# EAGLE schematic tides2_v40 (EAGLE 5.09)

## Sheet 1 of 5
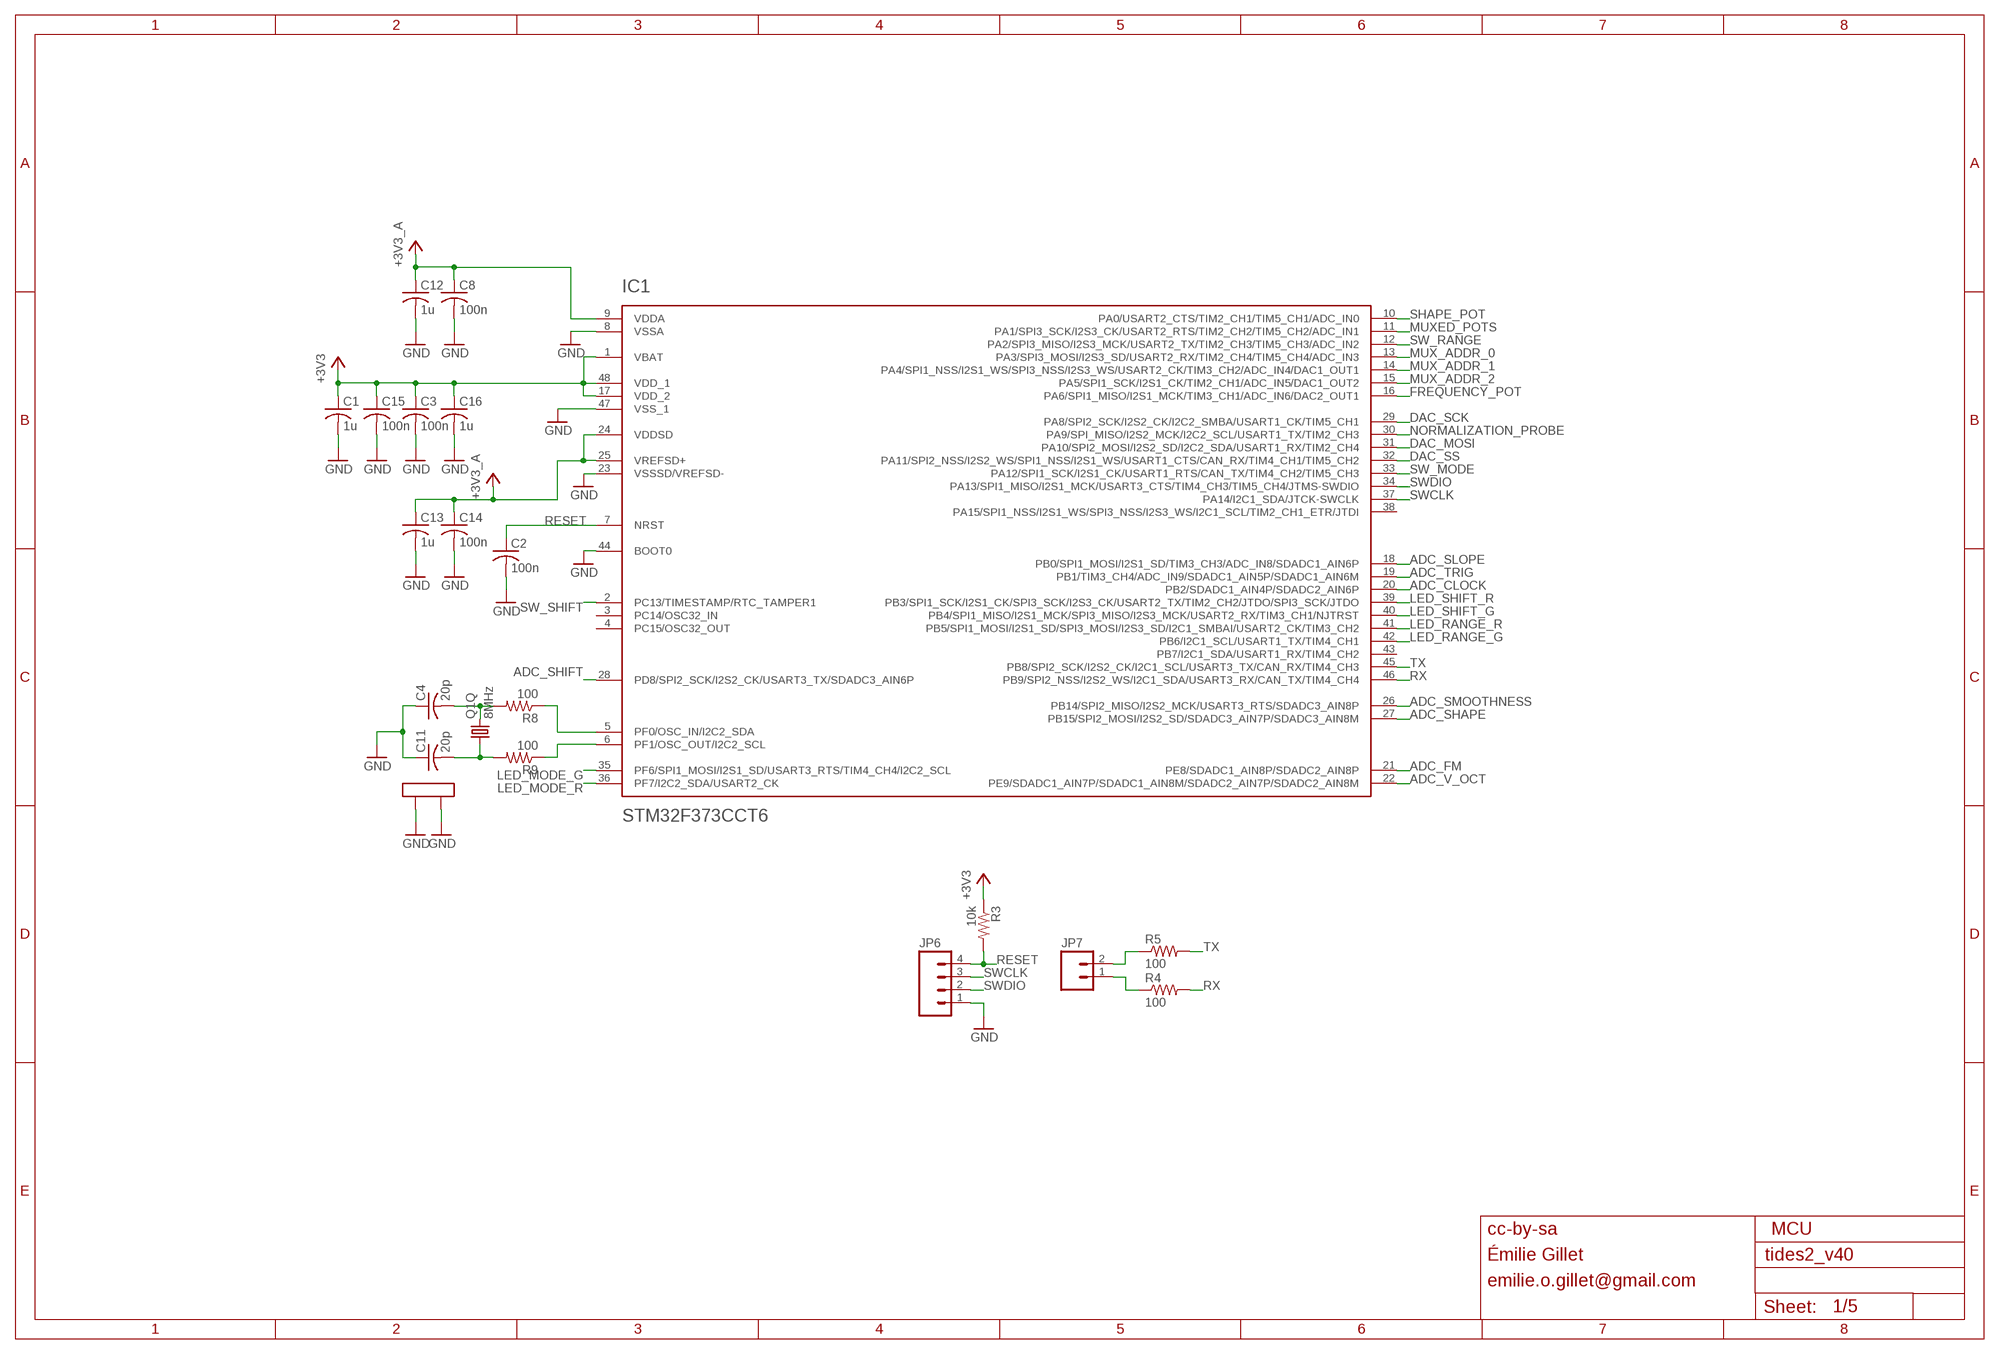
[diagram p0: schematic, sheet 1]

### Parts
C1  1u  C-USC0402  [C0402]
C2  100n  C-USC0402  [C0402]
C3  100n  C-USC0402  [C0402]
C4  20p  C-USC0402  [C0402]
C8  100n  C-USC0402  [C0402]
C11  20p  C-USC0402  [C0402]
C12  1u  C-USC0402  [C0402]
C13  1u  C-USC0402  [C0402]
C14  100n  C-USC0402  [C0402]
C15  100n  C-USC0402  [C0402]
C16  1u  C-USC0402  [C0402]
IC1  STM32F373CCT6  STM32F373C  [LQFP48]
JP6  M04PTH  [1X04]
JP7  M02PTH  [1X02]
Q1  8MHz  CRYSTAL  [CTS406]
R3  10k  R-US_R0402  [R0402]
R4  100  R-US_R0402  [R0402]
R5  100  R-US_R0402  [R0402]
R8  100  R-US_R0402  [R0402]
R9  100  R-US_R0402  [R0402]

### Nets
+3V3: C1.1 C3.1 C15.1 C16.1 IC1.1(VBAT) IC1.17(VDD_2) IC1.48(VDD_1) R3.1 ; also sheet 4,5
+3V3_A: C8.1 C12.1 C13.1 C14.1 IC1.9(VDDA) IC1.24(VDDSD) IC1.25(VREFSD+) ; also sheet 2,3,4,5
ADC_CLOCK: IC1.20(PB2/SDADC1_AIN4P/SDADC2_AIN6P) ; also sheet 3
ADC_FM: IC1.21(PE8/SDADC1_AIN8P/SDADC2_AIN8P) ; also sheet 3
ADC_SHAPE: IC1.27(PB15/SPI2_MOSI/I2S2_SD/SDADC3_AIN7P/SDADC3_AIN8M) ; also sheet 3
ADC_SHIFT: IC1.28(PD8/SPI2_SCK/I2S2_CK/USART3_TX/SDADC3_AIN6P) ; also sheet 3
ADC_SLOPE: IC1.18(PB0/SPI1_MOSI/I2S1_SD/TIM3_CH3/ADC_IN8/SDADC1_AIN6P) ; also sheet 3
ADC_SMOOTHNESS: IC1.26(PB14/SPI2_MISO/I2S2_MCK/USART3_RTS/SDADC3_AIN8P) ; also sheet 3
ADC_TRIG: IC1.19(PB1/TIM3_CH4/ADC_IN9/SDADC1_AIN5P/SDADC1_AIN6M) ; also sheet 3
ADC_V_OCT: IC1.22(PE9/SDADC1_AIN7P/SDADC1_AIN8M/SDADC2_AIN7P/SDADC2_AIN8M) ; also sheet 3
DAC_MOSI: IC1.31(PA10/SPI2_MOSI/I2S2_SD/I2C2_SDA/USART1_RX/TIM2_CH4) ; also sheet 4
DAC_SCK: IC1.29(PA8/SPI2_SCK/I2S2_CK/I2C2_SMBA/USART1_CK/TIM5_CH1) ; also sheet 4
DAC_SS: IC1.32(PA11/SPI2_NSS/I2S2_WS/SPI1_NSS/I2S1_WS/USART1_CTS/CAN_RX/TIM4_CH1/TIM5_CH2) ; also sheet 4
FREQUENCY_POT: IC1.16(PA6/SPI1_MISO/I2S1_MCK/TIM3_CH1/ADC_IN6/DAC2_OUT1) ; also sheet 2
GND: C1.2 C2.2 C3.2 C4.1 C8.2 C11.1 C12.2 C13.2 C14.2 C15.2 C16.2 IC1.8(VSSA) IC1.23(VSSSD/VREFSD-) IC1.44(BOOT0) IC1.47(VSS_1) JP6.1 Q1.2(LID1) Q1.4(LID2) ; also sheet 2,3,4,5
LED_MODE_G: IC1.35(PF6/SPI1_MOSI/I2S1_SD/USART3_RTS/TIM4_CH4/I2C2_SCL) ; also sheet 2
LED_MODE_R: IC1.36(PF7/I2C2_SDA/USART2_CK) ; also sheet 2
LED_RANGE_G: IC1.42(PB6/I2C1_SCL/USART1_TX/TIM4_CH1) ; also sheet 2
LED_RANGE_R: IC1.41(PB5/SPI1_MOSI/I2S1_SD/SPI3_MOSI/I2S3_SD/I2C1_SMBAI/USART2_CK/TIM3_CH2) ; also sheet 2
LED_SHIFT_G: IC1.40(PB4/SPI1_MISO/I2S1_MCK/SPI3_MISO/I2S3_MCK/USART2_RX/TIM3_CH1/NJTRST) ; also sheet 2
LED_SHIFT_R: IC1.39(PB3/SPI1_SCK/I2S1_CK/SPI3_SCK/I2S3_CK/USART2_TX/TIM2_CH2/JTDO/SPI3_SCK/JTDO) ; also sheet 2
MUX_ADDR_0: IC1.13(PA3/SPI3_MOSI/I2S3_SD/USART2_RX/TIM2_CH4/TIM5_CH4/ADC_IN3) ; also sheet 2
MUX_ADDR_1: IC1.14(PA4/SPI1_NSS/I2S1_WS/SPI3_NSS/I2S3_WS/USART2_CK/TIM3_CH2/ADC_IN4/DAC1_OUT1) ; also sheet 2
MUX_ADDR_2: IC1.15(PA5/SPI1_SCK/I2S1_CK/TIM2_CH1/ADC_IN5/DAC1_OUT2) ; also sheet 2
MUXED_POTS: IC1.11(PA1/SPI3_SCK/I2S3_CK/USART2_RTS/TIM2_CH2/TIM5_CH2/ADC_IN1) ; also sheet 2
N$7: IC1.5(PF0/OSC_IN/I2C2_SDA) R8.1
N$8: IC1.6(PF1/OSC_OUT/I2C2_SCL) R9.1
N$29: C4.2 Q1.3 R8.2
N$33: JP7.2 R5.1
N$35: C11.2 Q1.1 R9.2
N$51: JP7.1 R4.1
NORMALIZATION_PROBE: IC1.30(PA9/SPI_MISO/I2S2_MCK/I2C2_SCL/USART1_TX/TIM2_CH3) ; also sheet 3
RESET: C2.1 IC1.7(NRST) JP6.4 R3.2
RX: IC1.46(PB9/SPI2_NSS/I2S2_WS/I2C1_SDA/USART3_RX/CAN_TX/TIM4_CH4) R4.2
SHAPE_POT: IC1.10(PA0/USART2_CTS/TIM2_CH1/TIM5_CH1/ADC_IN0) ; also sheet 2
SW_MODE: IC1.33(PA12/SPI1_SCK/I2S1_CK/USART1_RTS/CAN_TX/TIM4_CH2/TIM5_CH3) ; also sheet 2
SW_RANGE: IC1.12(PA2/SPI3_MISO/I2S3_MCK/USART2_TX/TIM2_CH3/TIM5_CH3/ADC_IN2) ; also sheet 2
SW_SHIFT: IC1.2(PC13/TIMESTAMP/RTC_TAMPER1) ; also sheet 2
SWCLK: IC1.37(PA14/I2C1_SDA/JTCK-SWCLK) JP6.3
SWDIO: IC1.34(PA13/SPI1_MISO/I2S1_MCK/USART3_CTS/TIM4_CH3/TIM5_CH4/JTMS-SWDIO) JP6.2
TX: IC1.45(PB8/SPI2_SCK/I2S2_CK/I2C1_SCL/USART3_TX/CAN_RX/TIM4_CH3) R5.2
Unconnected: IC1.3(PC14/OSC32_IN) IC1.4(PC15/OSC32_OUT) IC1.38(PA15/SPI1_NSS/I2S1_WS/SPI3_NSS/I2S3_WS/I2C1_SCL/TIM2_CH1_ETR/JTDI) IC1.43(PB7/I2C1_SDA/USART1_RX/TIM4_CH2)

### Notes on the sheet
- cc-by-sa | MCU
- Émilie Gillet
- emilie.o.gillet@gmail.com

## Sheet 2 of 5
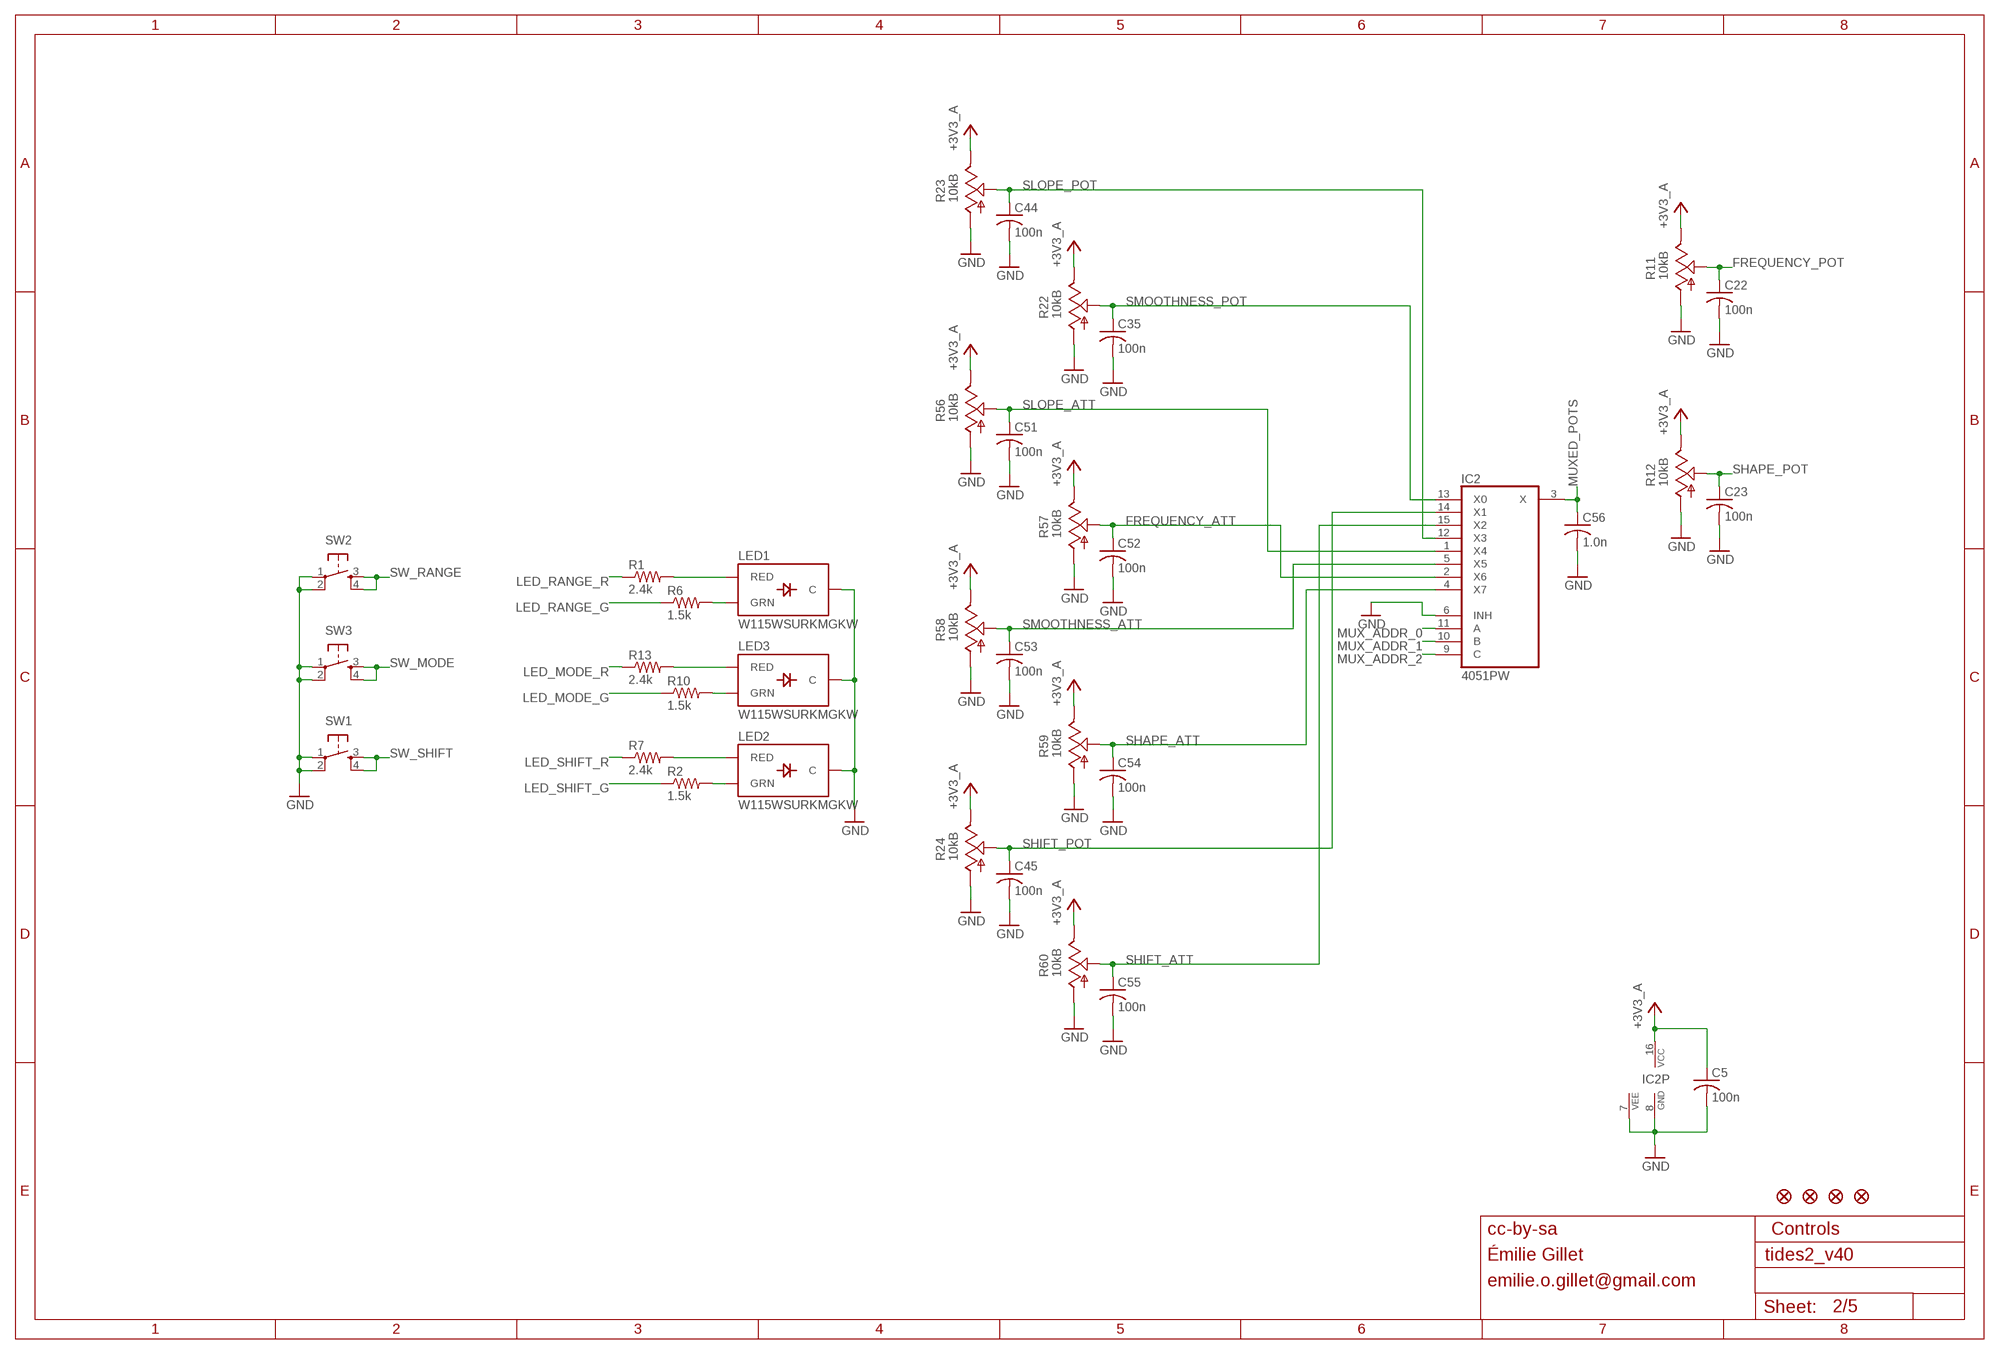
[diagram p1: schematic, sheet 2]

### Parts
C5  100n  C-USC0402  [C0402]
C22  100n  C-USC0402  [C0402]
C23  100n  C-USC0402  [C0402]
C35  100n  C-USC0402  [C0402]
C44  100n  C-USC0402  [C0402]
C45  100n  C-USC0402  [C0402]
C51  100n  C-USC0402  [C0402]
C52  100n  C-USC0402  [C0402]
C53  100n  C-USC0402  [C0402]
C54  100n  C-USC0402  [C0402]
C55  100n  C-USC0402  [C0402]
C56  1.0n  C-USC0402  [C0402]
IC2  4051PW  [TSSOP16_065]
JP1  FIDUCIAL1X2  [FIDUCIAL-1X2]
JP2  FIDUCIAL1X2  [FIDUCIAL-1X2]
JP3  FIDUCIAL1X2  [FIDUCIAL-1X2]
JP4  FIDUCIAL1X2  [FIDUCIAL-1X2]
LED1  W115WSURKMGKW  LED-BICOLOR-THROUGHHOLE2.54  [LED-BICOLOR-THROUGHHOLE-2.54]
LED2  W115WSURKMGKW  LED-BICOLOR-THROUGHHOLE2.54  [LED-BICOLOR-THROUGHHOLE-2.54]
LED3  W115WSURKMGKW  LED-BICOLOR-THROUGHHOLE2.54  [LED-BICOLOR-THROUGHHOLE-2.54]
R1  2.4k  R-US_R0402  [R0402]
R2  1.5k  R-US_R0402  [R0402]
R6  1.5k  R-US_R0402  [R0402]
R7  2.4k  R-US_R0402  [R0402]
R10  1.5k  R-US_R0402  [R0402]
R11  10kB  POT_USVERTICAL_PS  [ALPS_POT_VERTICAL_PS]
R12  10kB  POT_USVERTICAL_PS  [ALPS_POT_VERTICAL_PS]
R13  2.4k  R-US_R0402  [R0402]
R22  10kB  POT_USVERTICAL_PS  [ALPS_POT_VERTICAL_PS]
R23  10kB  POT_USVERTICAL_PS  [ALPS_POT_VERTICAL_PS]
R24  10kB  POT_USVERTICAL_PS  [ALPS_POT_VERTICAL_PS]
R56  10kB  POT_USVERTICAL  [ALPS_POT_VERTICAL]
R57  10kB  POT_USVERTICAL  [ALPS_POT_VERTICAL]
R58  10kB  POT_USVERTICAL  [ALPS_POT_VERTICAL]
R59  10kB  POT_USVERTICAL  [ALPS_POT_VERTICAL]
R60  10kB  POT_USVERTICAL  [ALPS_POT_VERTICAL]
SW1  TAC_SWITCHPTH  [TACTILE-PTH]
SW2  TAC_SWITCHPTH  [TACTILE-PTH]
SW3  TAC_SWITCHPTH  [TACTILE-PTH]

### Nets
+3V3_A: C5.1 IC2.16(VCC) R11.P$1(E) R12.P$1(E) R22.P$1(E) R23.P$1(E) R24.P$1(E) R56.P$1(E) R57.P$1(E) R58.P$1(E) R59.P$1(E) R60.P$1(E) ; also sheet 1,3,4,5
FREQUENCY_ATT: C52.1 IC2.2(X6) R57.P$2(S)
FREQUENCY_POT: C22.1 R11.P$2(S) ; also sheet 1
GND: C5.2 C22.2 C23.2 C35.2 C44.2 C45.2 C51.2 C52.2 C53.2 C54.2 C55.2 C56.2 IC2.6(INH) IC2.7(VEE) IC2.8(GND) LED1.2(C) LED2.2(C) LED3.2(C) R11.P$3(A) R12.P$3(A) R22.P$3(A) R23.P$3(A) R24.P$3(A) R56.P$3(A) R57.P$3(A) R58.P$3(A) R59.P$3(A) R60.P$3(A) SW1.1 SW1.2 SW2.1 SW2.2 SW3.1 SW3.2 ; also sheet 1,3,4,5
LED_MODE_G: R10.1 ; also sheet 1
LED_MODE_R: R13.1 ; also sheet 1
LED_RANGE_G: R6.1 ; also sheet 1
LED_RANGE_R: R1.1 ; also sheet 1
LED_SHIFT_G: R2.1 ; also sheet 1
LED_SHIFT_R: R7.1 ; also sheet 1
MUX_ADDR_0: IC2.11(A) ; also sheet 1
MUX_ADDR_1: IC2.10(B) ; also sheet 1
MUX_ADDR_2: IC2.9(C) ; also sheet 1
MUXED_POTS: C56.1 IC2.3(X) ; also sheet 1
N$16: LED1.3(RED) R1.2
N$18: LED3.3(RED) R13.2
N$20: LED3.1(GRN) R10.2
N$21: LED2.3(RED) R7.2
N$22: LED1.1(GRN) R6.2
N$23: LED2.1(GRN) R2.2
SHAPE_ATT: C54.1 IC2.4(X7) R59.P$2(S)
SHAPE_POT: C23.1 R12.P$2(S) ; also sheet 1
SHIFT_ATT: C55.1 IC2.15(X2) R60.P$2(S)
SHIFT_POT: C45.1 IC2.14(X1) R24.P$2(S)
SLOPE_ATT: C51.1 IC2.1(X4) R56.P$2(S)
SLOPE_POT: C44.1 IC2.12(X3) R23.P$2(S)
SMOOTHNESS_ATT: C53.1 IC2.5(X5) R58.P$2(S)
SMOOTHNESS_POT: C35.1 IC2.13(X0) R22.P$2(S)
SW_MODE: SW3.3 SW3.4 ; also sheet 1
SW_RANGE: SW2.3 SW2.4 ; also sheet 1
SW_SHIFT: SW1.3 SW1.4 ; also sheet 1

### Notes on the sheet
- cc-by-sa | Controls
- Émilie Gillet
- emilie.o.gillet@gmail.com

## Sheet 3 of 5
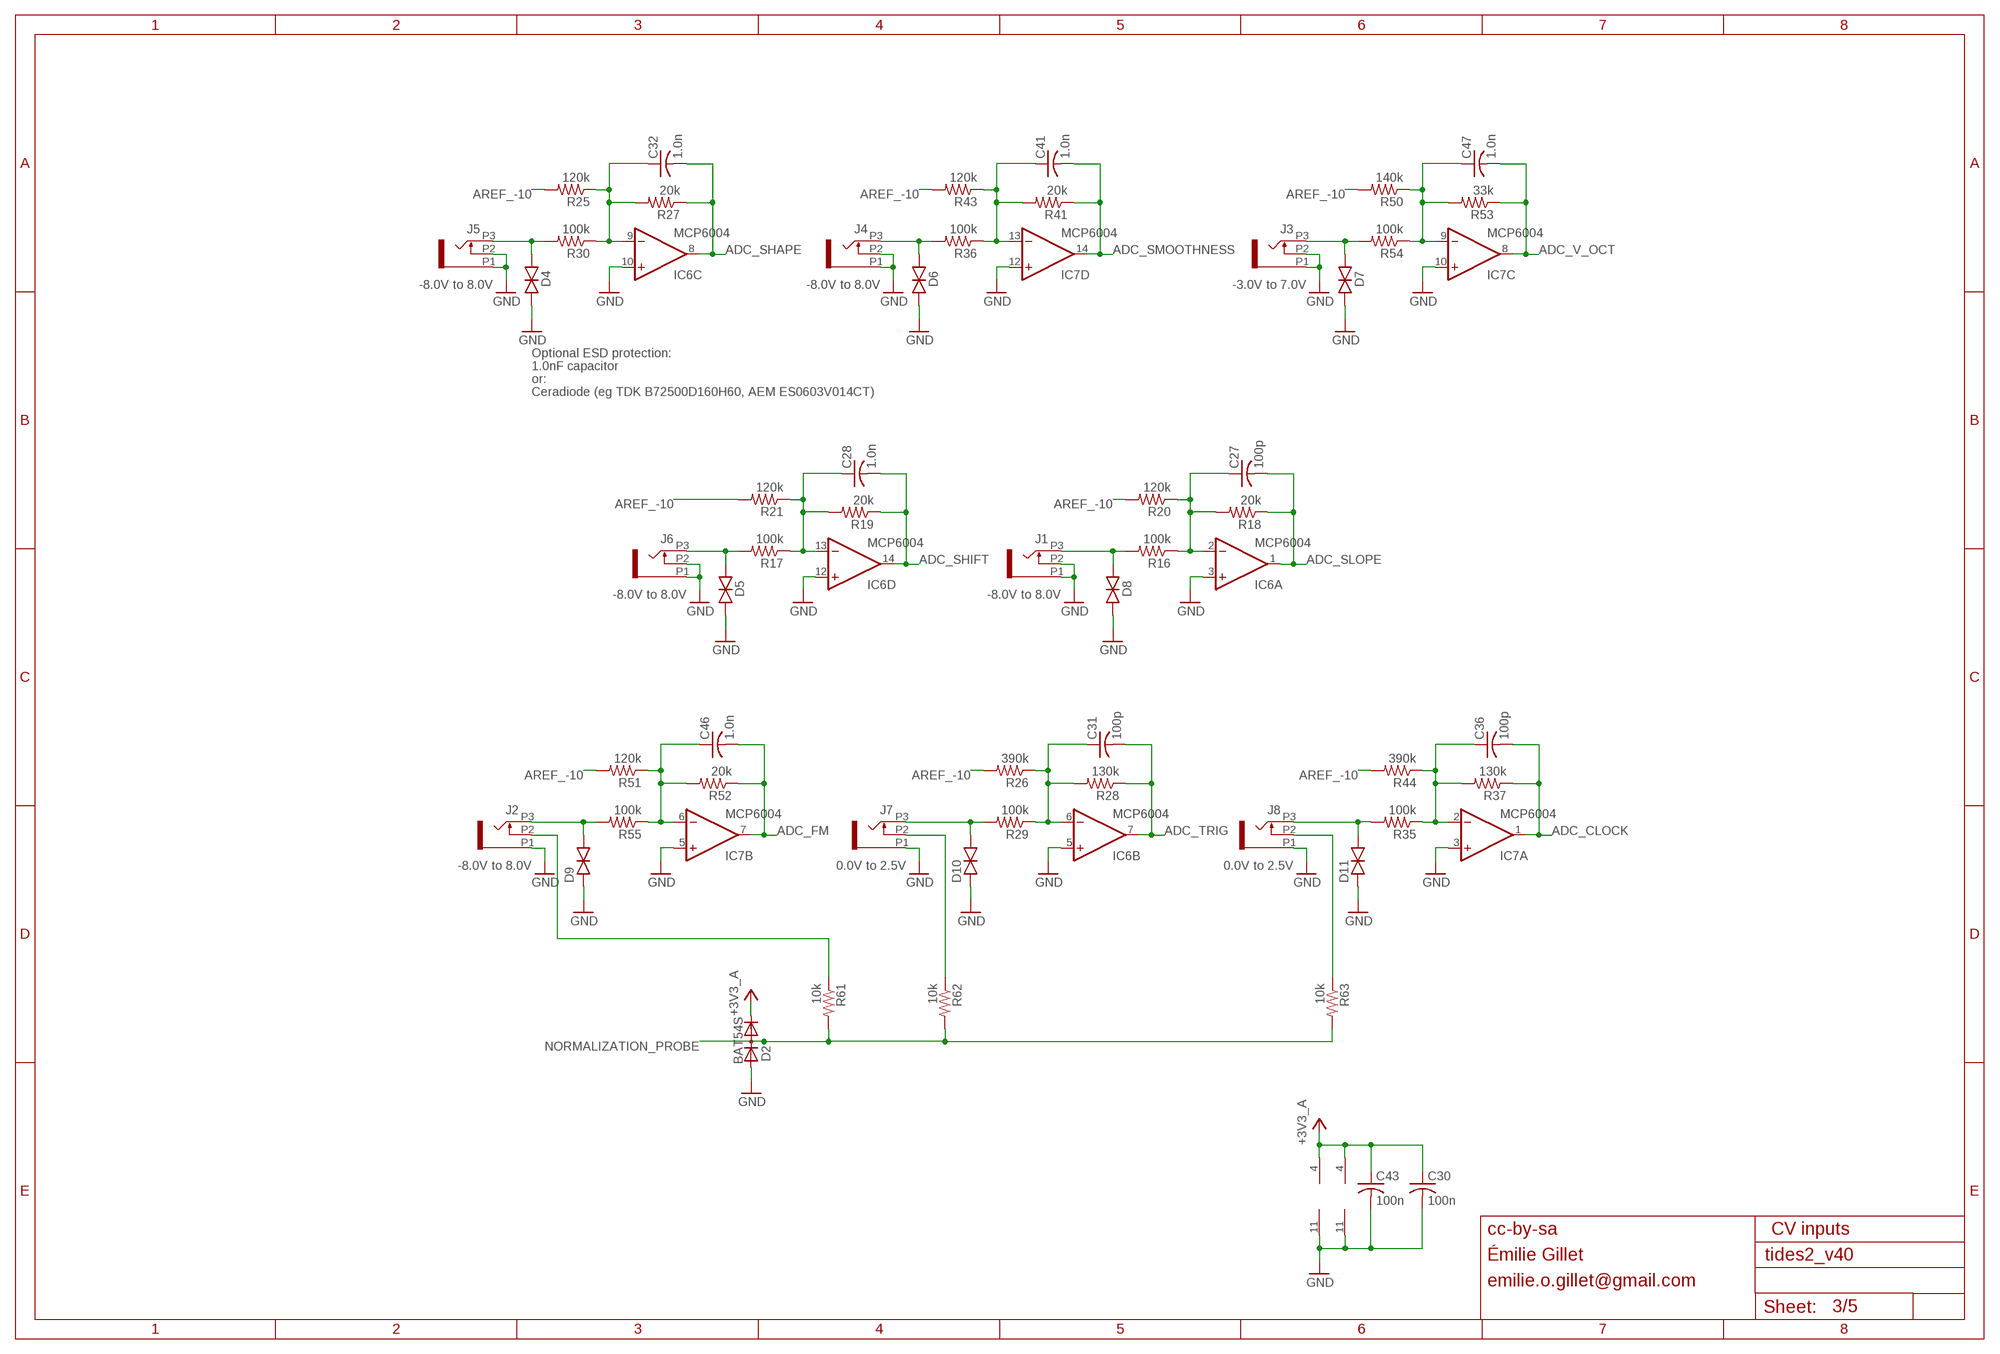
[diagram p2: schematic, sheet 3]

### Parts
C27  100p  C-USC0402  [C0402]
C28  1.0n  C-USC0402  [C0402]
C30  100n  C-USC0402  [C0402]
C31  100p  C-USC0402  [C0402]
C32  1.0n  C-USC0402  [C0402]
C36  100p  C-USC0402  [C0402]
C41  1.0n  C-USC0402  [C0402]
C43  100n  C-USC0402  [C0402]
C46  1.0n  C-USC0402  [C0402]
C47  1.0n  C-USC0402  [C0402]
D2  BAT54S  DIODE_2CACA-SOT23  [SOT23]
D4  TVS  [0603]
D5  TVS  [0603]
D6  TVS  [0603]
D7  TVS  [0603]
D8  TVS  [0603]
D9  TVS  [0603]
D10  TVS  [0603]
D11  TVS  [0603]
IC6  MCP6004  TL074PW  [TSSOP14_065]
IC7  MCP6004  TL074PW  [TSSOP14_065]
J1  PJ301_THONKICONN6  [WQP_PJ_301M6]
J2  PJ301_THONKICONN6  [WQP_PJ_301M6]
J3  PJ301_THONKICONN6  [WQP_PJ_301M6]
J4  PJ301_THONKICONN6  [WQP_PJ_301M6]
J5  PJ301_THONKICONN6  [WQP_PJ_301M6]
J6  PJ301_THONKICONN6  [WQP_PJ_301M6]
J7  PJ301_THONKICONN6  [WQP_PJ_301M6]
J8  PJ301_THONKICONN6  [WQP_PJ_301M6]
R16  100k  R-US_R0402  [R0402]
R17  100k  R-US_R0402  [R0402]
R18  20k  R-US_R0402  [R0402]
R19  20k  R-US_R0402  [R0402]
R20  120k  R-US_R0402  [R0402]
R21  120k  R-US_R0402  [R0402]
R25  120k  R-US_R0402  [R0402]
R26  390k  R-US_R0402  [R0402]
R27  20k  R-US_R0402  [R0402]
R28  130k  R-US_R0402  [R0402]
R29  100k  R-US_R0402  [R0402]
R30  100k  R-US_R0402  [R0402]
R35  100k  R-US_R0402  [R0402]
R36  100k  R-US_R0402  [R0402]
R37  130k  R-US_R0402  [R0402]
R41  20k  R-US_R0402  [R0402]
R43  120k  R-US_R0402  [R0402]
R44  390k  R-US_R0402  [R0402]
R50  140k  R-US_R0402  [R0402]
R51  120k  R-US_R0402  [R0402]
R52  20k  R-US_R0402  [R0402]
R53  33k  R-US_R0402  [R0402]
R54  100k  R-US_R0402  [R0402]
R55  100k  R-US_R0402  [R0402]
R61  10k  R-US_R0402  [R0402]
R62  10k  R-US_R0402  [R0402]
R63  10k  R-US_R0402  [R0402]

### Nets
+3V3_A: C30.1 C43.1 D2.2(C) IC6.4(P:V+) IC7.4(P:V+) ; also sheet 1,2,4,5
ADC_CLOCK: C36.2 IC7.1(A:OUT) R37.1 ; also sheet 1
ADC_FM: C46.2 IC7.7(B:OUT) R52.1 ; also sheet 1
ADC_SHAPE: C32.2 IC6.8(C:OUT) R27.1 ; also sheet 1
ADC_SHIFT: C28.2 IC6.14(D:OUT) R19.1 ; also sheet 1
ADC_SLOPE: C27.2 IC6.1(A:OUT) R18.1 ; also sheet 1
ADC_SMOOTHNESS: C41.2 IC7.14(D:OUT) R41.1 ; also sheet 1
ADC_TRIG: C31.2 IC6.7(B:OUT) R28.1 ; also sheet 1
ADC_V_OCT: C47.2 IC7.8(C:OUT) R53.1 ; also sheet 1
AREF_-10: R20.2 R21.2 R25.2 R26.2 R43.2 R44.2 R50.2 R51.2 ; also sheet 5
CLOCK_IN: D11.2(C) J8.P3 R35.2
FM_IN: D9.2(C) J2.P3 R55.2
GND: C30.2 C43.2 D2.1(A) D4.1(A) D5.1(A) D6.1(A) D7.1(A) D8.1(A) D9.1(A) D10.1(A) D11.1(A) IC6.3(A:+IN) IC6.5(B:+IN) IC6.10(C:+IN) IC6.11(P:V-) IC6.12(D:+IN) IC7.3(A:+IN) IC7.5(B:+IN) IC7.10(C:+IN) IC7.11(P:V-) IC7.12(D:+IN) J1.P1 J1.P2 J2.P1 J3.P1 J3.P2 J4.P1 J4.P2 J5.P1 J5.P2 J6.P1 J6.P2 J7.P1 J8.P1 ; also sheet 1,2,4,5
N$2: J7.P2 R62.1
N$3: J8.P2 R63.1
N$4: C27.1 IC6.2(A:-IN) R16.1 R18.2 R20.1
N$26: J2.P2 R61.1
N$28: C28.1 IC6.13(D:-IN) R17.1 R19.2 R21.1
N$30: C47.1 IC7.9(C:-IN) R50.1 R53.2 R54.1
N$32: C46.1 IC7.6(B:-IN) R51.1 R52.2 R55.1
N$34: C31.1 IC6.6(B:-IN) R26.1 R28.2 R29.1
N$37: C32.1 IC6.9(C:-IN) R25.1 R27.2 R30.1
N$39: C36.1 IC7.2(A:-IN) R35.1 R37.2 R44.1
N$41: C41.1 IC7.13(D:-IN) R36.1 R41.2 R43.1
NORMALIZATION_PROBE: D2.3(AC) R61.2 R62.2 R63.2 ; also sheet 1
SHAPE_IN: D4.2(C) J5.P3 R30.2
SHIFT_IN: D5.2(C) J6.P3 R17.2
SLOPE_IN: D8.2(C) J1.P3 R16.2
SMOOTHNESS_IN: D6.2(C) J4.P3 R36.2
TRIG_IN: D10.2(C) J7.P3 R29.2
V_OCT_IN: D7.2(C) J3.P3 R54.2

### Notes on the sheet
- -8.0V to 8.0V | -8.0V to 8.0V | -3.0V to 7.0V
- Optional ESD protection:
- 1.0nF capacitor
- or:
- Ceradiode (eg TDK B72500D160H60, AEM ES0603V014CT)
- -8.0V to 8.0V | -8.0V to 8.0V
- -8.0V to 8.0V | 0.0V to 2.5V | 0.0V to 2.5V
- cc-by-sa | CV inputs
- Émilie Gillet
- emilie.o.gillet@gmail.com

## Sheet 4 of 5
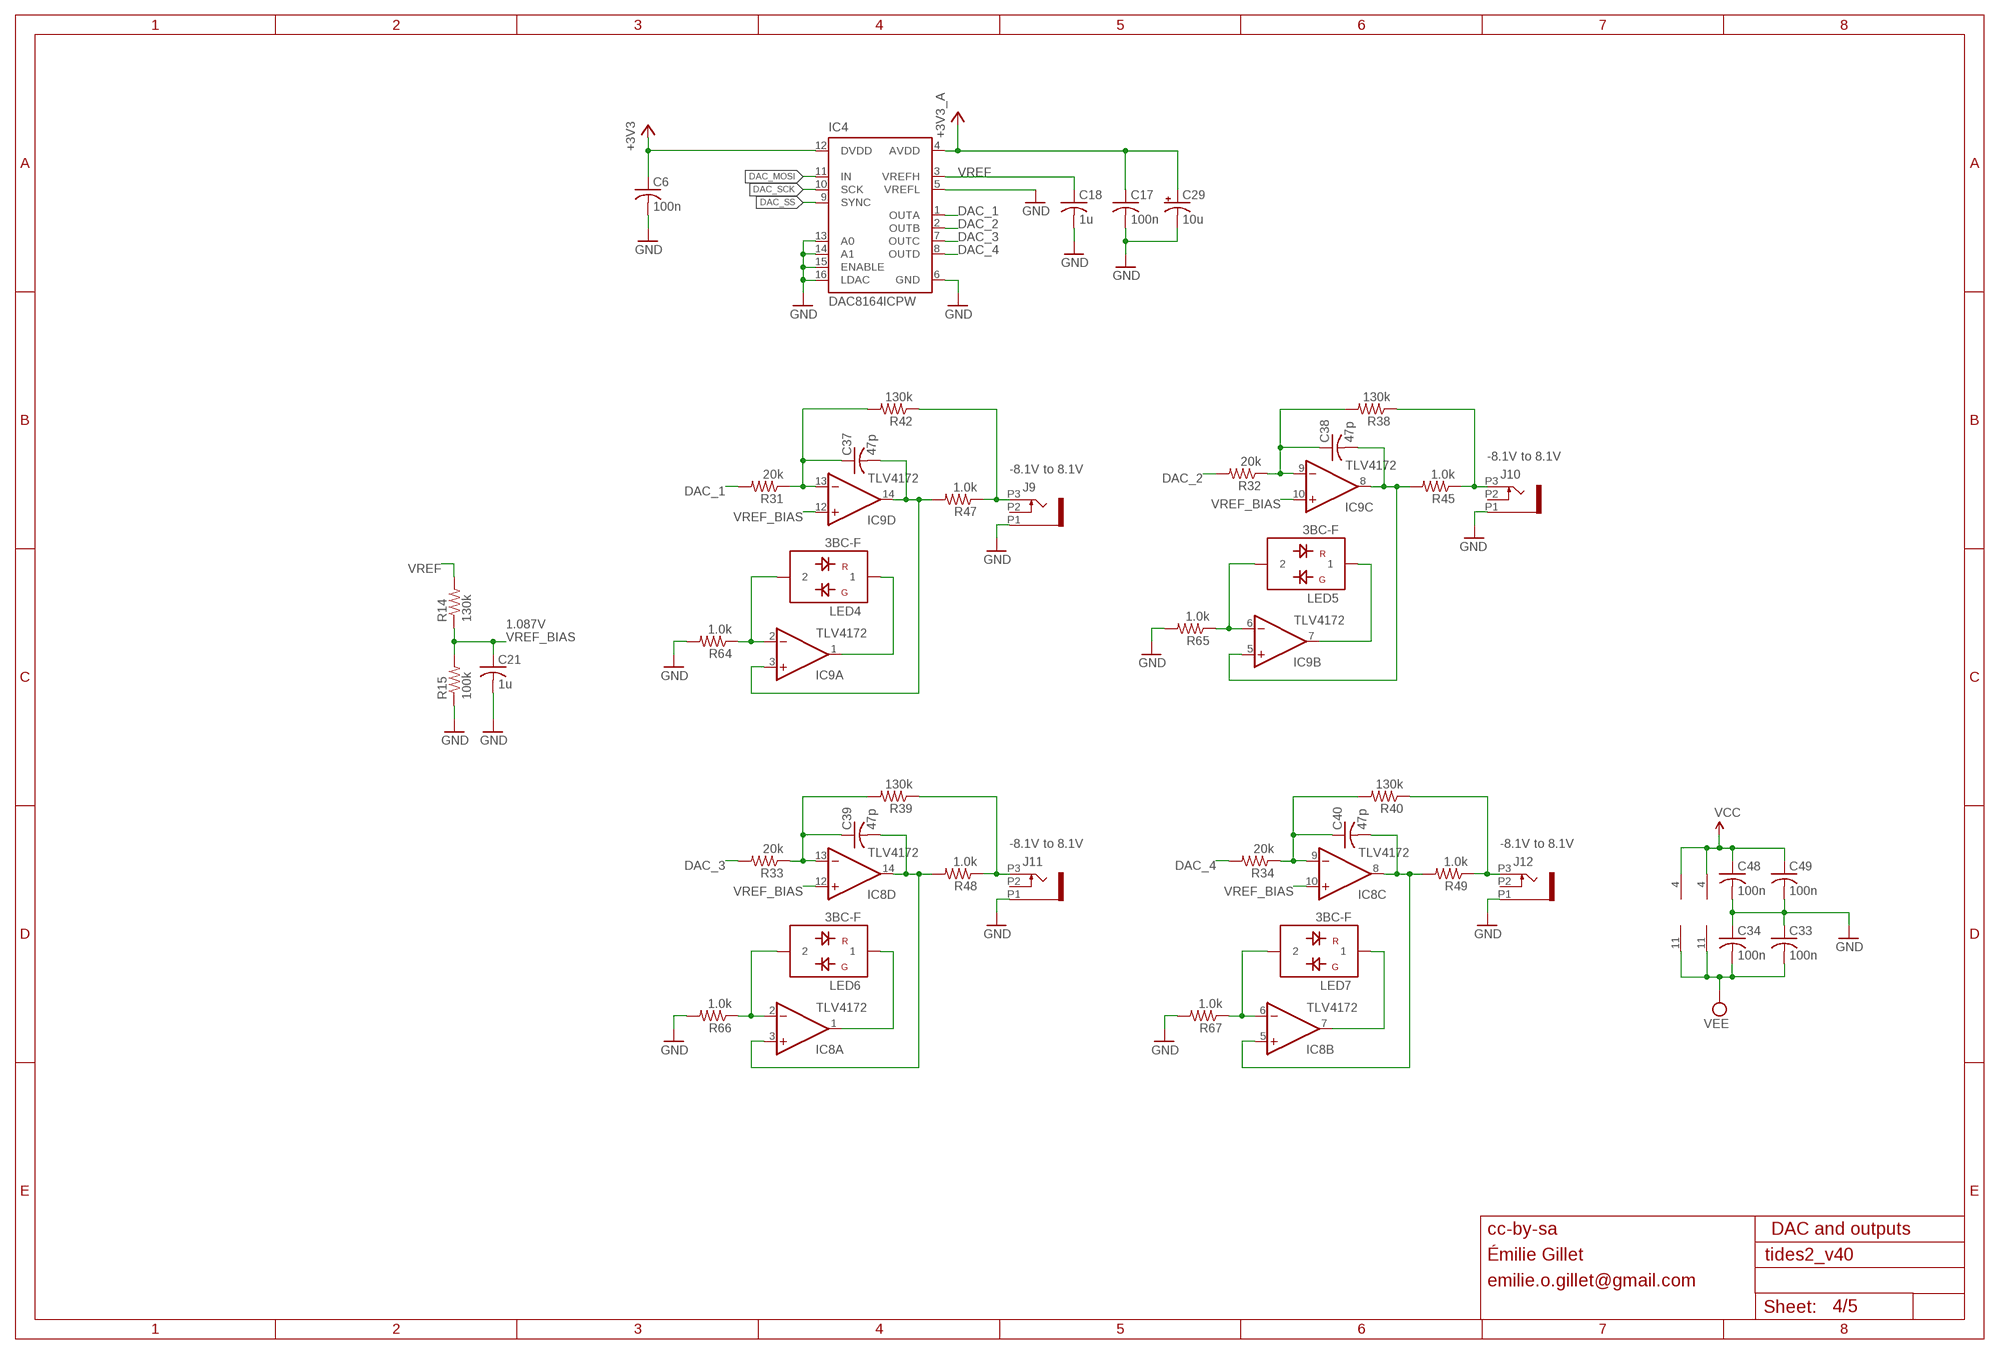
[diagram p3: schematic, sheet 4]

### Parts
C6  100n  C-USC0402  [C0402]
C17  100n  C-USC0402  [C0402]
C18  1u  C-USC0402  [C0402]
C21  1u  C-USC0402  [C0402]
C29  10u  CPOL-USA  [PANASONIC_A]
C33  100n  C-USC0402  [C0402]
C34  100n  C-USC0402  [C0402]
C37  47p  C-USC0402  [C0402]
C38  47p  C-USC0402  [C0402]
C39  47p  C-USC0402  [C0402]
C40  47p  C-USC0402  [C0402]
C48  100n  C-USC0402  [C0402]
C49  100n  C-USC0402  [C0402]
IC4  DAC8164ICPW  DAC8564  [SOP65P640X110-16N]
IC8  TLV4172  TL074PW  [TSSOP14_065]
IC9  TLV4172  TL074PW  [TSSOP14_065]
J9  PJ301_THONKICONN6  [WQP_PJ_301M6]
J10  PJ301_THONKICONN6  [WQP_PJ_301M6]
J11  PJ301_THONKICONN6  [WQP_PJ_301M6]
J12  PJ301_THONKICONN6  [WQP_PJ_301M6]
LED4  3BC-F  LED-BICOLOR-SHARED-THROUGHHOLE  [LED3MM]
LED5  3BC-F  LED-BICOLOR-SHARED-THROUGHHOLE  [LED3MM]
LED6  3BC-F  LED-BICOLOR-SHARED-THROUGHHOLE  [LED3MM]
LED7  3BC-F  LED-BICOLOR-SHARED-THROUGHHOLE  [LED3MM]
R14  130k  R-US_R0402  [R0402]
R15  100k  R-US_R0402  [R0402]
R31  20k  R-US_R0402  [R0402]
R32  20k  R-US_R0402  [R0402]
R33  20k  R-US_R0402  [R0402]
R34  20k  R-US_R0402  [R0402]
R38  130k  R-US_R0402  [R0402]
R39  130k  R-US_R0402  [R0402]
R40  130k  R-US_R0402  [R0402]
R42  130k  R-US_R0402  [R0402]
R45  1.0k  R-US_R0603  [R0603]
R47  1.0k  R-US_R0603  [R0603]
R48  1.0k  R-US_R0603  [R0603]
R49  1.0k  R-US_R0603  [R0603]
R64  1.0k  R-US_R0402  [R0402]
R65  1.0k  R-US_R0402  [R0402]
R66  1.0k  R-US_R0402  [R0402]
R67  1.0k  R-US_R0402  [R0402]

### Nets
+3V3: C6.1 IC4.12(DVDD) ; also sheet 1,5
+3V3_A: C17.1 C29.+ IC4.4(AVDD) ; also sheet 1,2,3,5
DAC_1: IC4.1(OUTA) R31.2
DAC_2: IC4.2(OUTB) R32.2
DAC_3: IC4.7(OUTC) R33.2
DAC_4: IC4.8(OUTD) R34.2
DAC_MOSI: IC4.11(IN) ; also sheet 1
DAC_SCK: IC4.10(SCK) ; also sheet 1
DAC_SS: IC4.9(SYNC) ; also sheet 1
GND: C6.2 C17.2 C18.2 C21.2 C29.- C33.1 C34.1 C48.2 C49.2 IC4.5(VREFL) IC4.6(GND) IC4.13(A0) IC4.14(A1) IC4.15(ENABLE) IC4.16(LDAC) J9.P1 J10.P1 J11.P1 J12.P1 R15.1 R64.2 R65.2 R66.2 R67.2 ; also sheet 1,2,3,5
N$45: C37.2 IC9.3(A:+IN) IC9.14(D:OUT) R47.2
N$49: J11.P3 R39.1 R48.1
N$53: J9.P3 R42.1 R47.1
N$54: C39.1 IC8.13(D:-IN) R33.1 R39.2
N$58: J12.P3 R40.1 R49.1
N$59: C40.1 IC8.9(C:-IN) R34.1 R40.2
N$60: C38.1 IC9.9(C:-IN) R32.1 R38.2
N$61: C37.1 IC9.13(D:-IN) R31.1 R42.2
N$63: J10.P3 R38.1 R45.1
N$67: IC9.2(A:-IN) LED4.2 R64.1
N$68: IC9.1(A:OUT) LED4.1
N$70: C38.2 IC9.5(B:+IN) IC9.8(C:OUT) R45.2
N$71: IC9.6(B:-IN) LED5.2 R65.1
N$72: IC9.7(B:OUT) LED5.1
N$73: C39.2 IC8.3(A:+IN) IC8.14(D:OUT) R48.2
N$74: IC8.2(A:-IN) LED6.2 R66.1
N$75: IC8.1(A:OUT) LED6.1
N$76: C40.2 IC8.5(B:+IN) IC8.8(C:OUT) R49.2
N$77: IC8.6(B:-IN) LED7.2 R67.1
N$78: IC8.7(B:OUT) LED7.1
VCC: C48.1 C49.1 IC8.4(P:V+) IC9.4(P:V+) ; also sheet 5
VEE: C33.2 C34.2 IC8.11(P:V-) IC9.11(P:V-) ; also sheet 5
VREF: C18.1 IC4.3(VREFH) R14.2
VREF_BIAS: C21.1 IC8.10(C:+IN) IC8.12(D:+IN) IC9.10(C:+IN) IC9.12(D:+IN) R14.1 R15.2
Unconnected: J9.P2 J10.P2 J11.P2 J12.P2

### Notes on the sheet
- -8.1V to 8.1V
- -8.1V to 8.1V
- 1.087V
- -8.1V to 8.1V | -8.1V to 8.1V
- cc-by-sa | DAC and outputs
- Émilie Gillet
- emilie.o.gillet@gmail.com

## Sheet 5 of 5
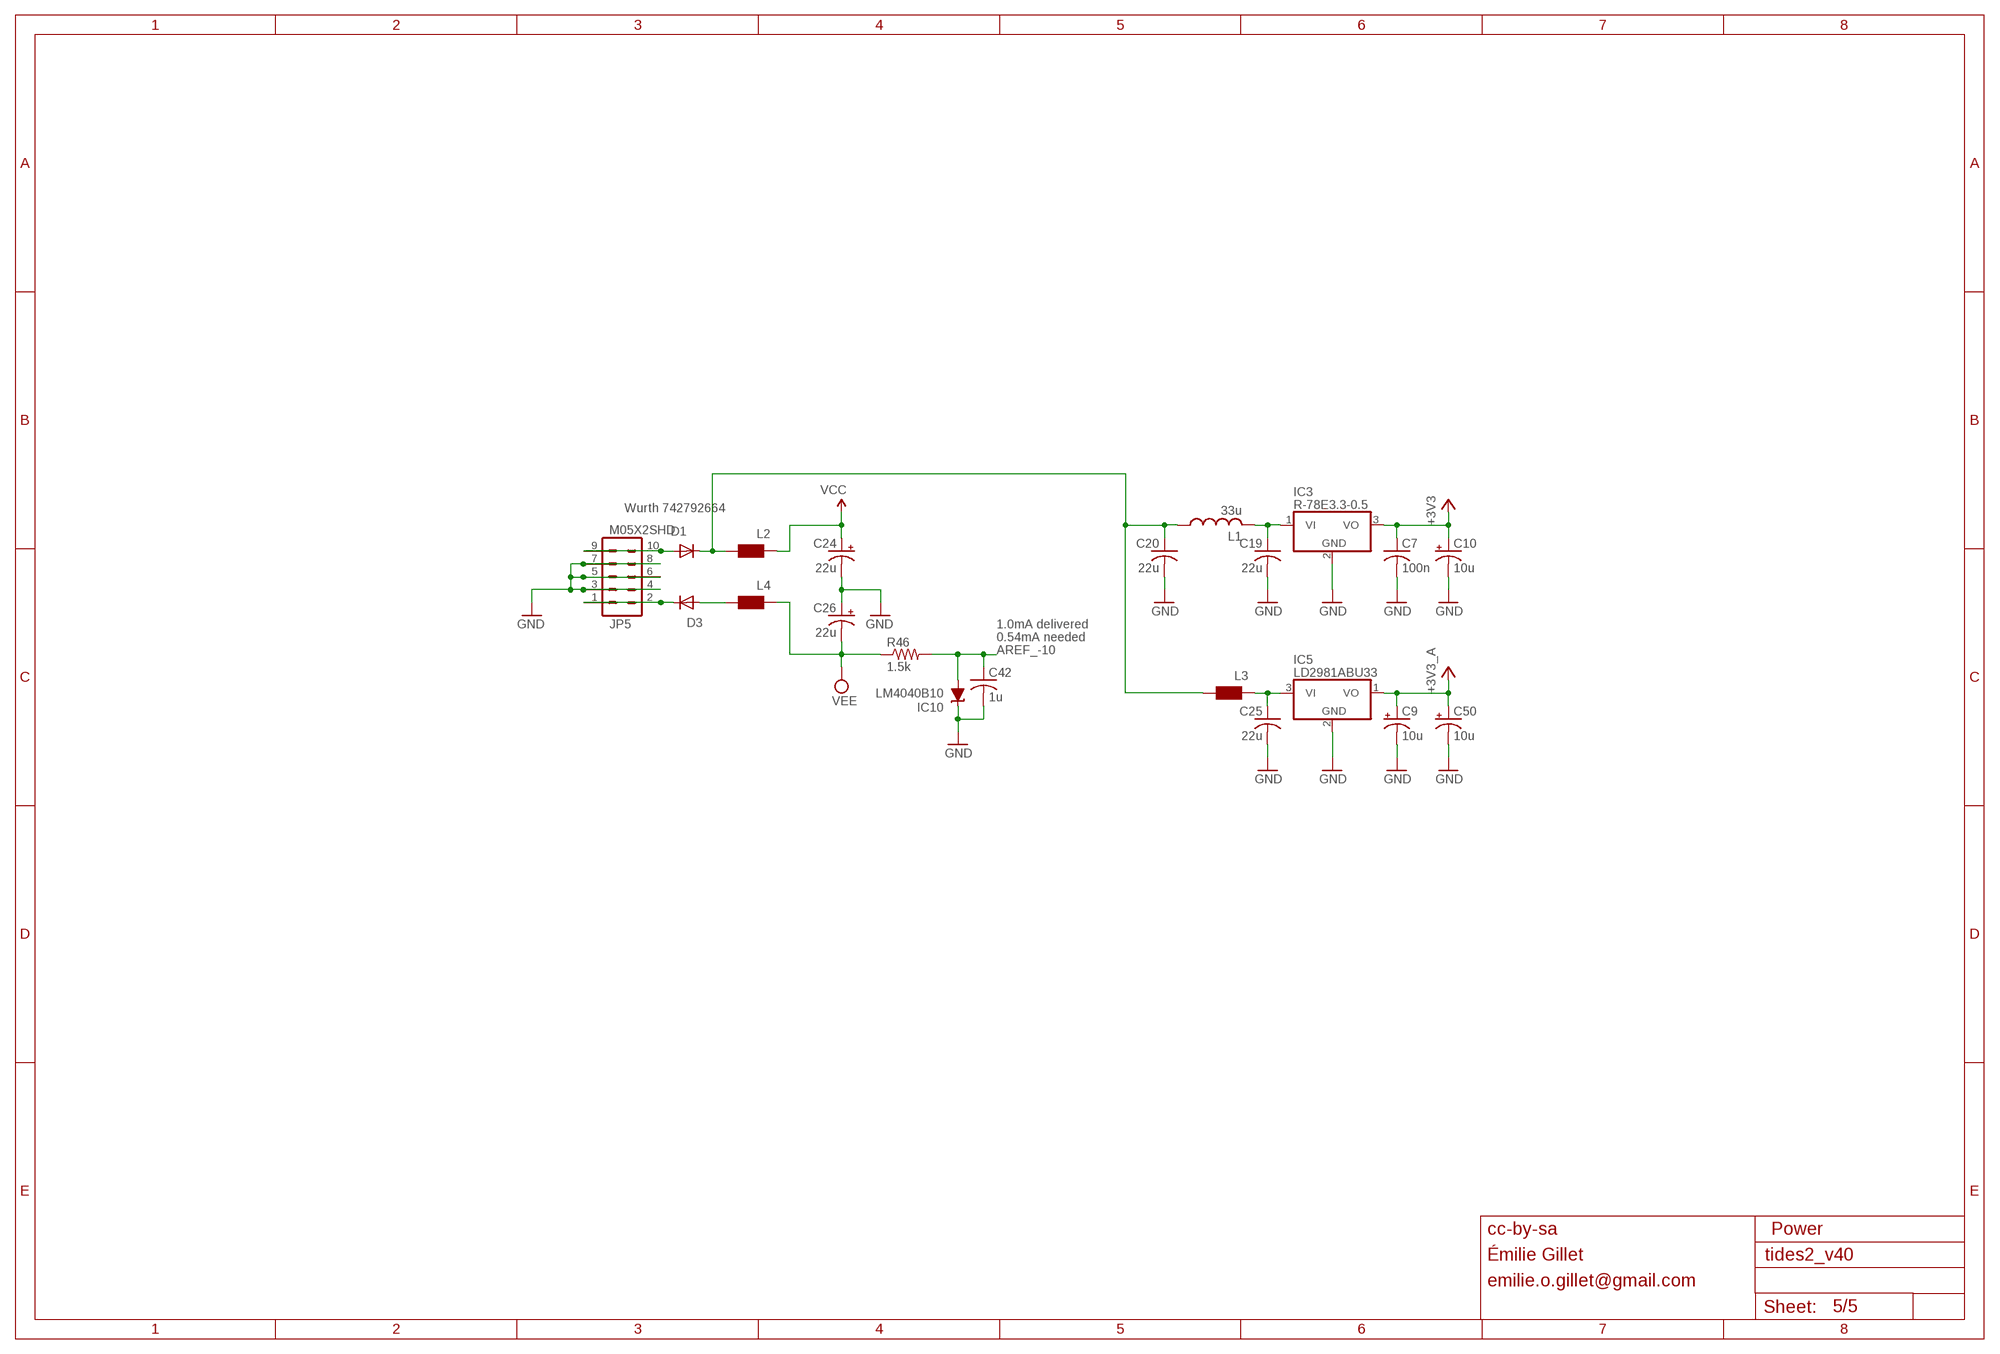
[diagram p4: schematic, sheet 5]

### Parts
C7  100n  C-USC0402  [C0402]
C9  10u  CPOL-USA  [PANASONIC_A]
C10  10u  CPOL-USA  [PANASONIC_A]
C19  22u  C-USC1206  [C1206]
C20  22u  C-USC1206  [C1206]
C24  22u  CPOL-USB  [PANASONIC_B]
C25  22u  C-USC1206  [C1206]
C26  22u  CPOL-USB  [PANASONIC_B]
C42  1u  C-USC0402  [C0402]
C50  10u  CPOL-USA  [PANASONIC_A]
D1  1N5819HW  DIODE-SOD123  [SOD123]
D3  1N5819HW  DIODE-SOD123  [SOD123]
IC3  R-78E3.3-0.5  WE173950378  [WE78]
IC5  LD2981ABU33  LD2981ABU  [SOT89]
IC10  LM4040B10  LM4041B12DBZ  [DBZ_R-PDSO-G3]
JP5  M05X2SHD  [2X5-SHROUDED]
L1  33u  L-USL2012C  [L2012C]
L2  WE-CBF_0603  [0603]
L3  WE-CBF_0603  [0603]
L4  WE-CBF_0603  [0603]
R46  1.5k  R-US_R0402  [R0402]

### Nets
+3V3: C7.1 C10.+ IC3.3(VO) ; also sheet 1,4
+3V3_A: C9.+ C50.+ IC5.1(VO) ; also sheet 1,2,3,4
AREF_-10: C42.1 IC10.2(A) R46.2 ; also sheet 3
GND: C7.2 C9.- C10.- C19.2 C20.2 C24.- C25.2 C26.+ C42.2 C50.- IC3.2(GND) IC5.2(GND) IC10.1(C) JP5.3 JP5.4 JP5.5 JP5.6 JP5.7 JP5.8 ; also sheet 1,2,3,4
N$1: C19.1 IC3.1(VI) L1.2
N$38: D3.A L4.2
N$40: C20.1 D1.C L1.1 L2.2 L3.2
N$42: C25.1 IC5.3(VI) L3.1
N$56: D1.A JP5.9 JP5.10
N$64: D3.C JP5.1 JP5.2
VCC: C24.+ L2.1 ; also sheet 4
VEE: C26.- L4.1 R46.1 ; also sheet 4

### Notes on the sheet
- Wurth 742792664
- 1.0mA delivered
- 0.54mA needed
- cc-by-sa | Power
- Émilie Gillet
- emilie.o.gillet@gmail.com

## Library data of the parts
C1-C8 C11-C23 C25 C27 C28 C30-C49 C51-C56 = rcl:C-US: CAPACITOR, American symbol
C9 C10 C24 C26 C29 C50 = rcl:CPOL-US: POLARIZED CAPACITOR, American symbol
D1 D3 = diode:DIODE-: DIODE
D2 = diode:DIODE_2CACA-: 2 Diodes - Cathode-Anode|Cathode-Anode
D4-D11 = og-diodes:TVS
IC1 = og-stm32f2:STM32F373C
IC2 = og-ics:4051: 8-channel ANALOG MULTIPLEXER
IC3 = og-vreg:WE173950378
IC4 = og-dac:DAC8564
IC5 = og-vreg:LD2981
IC6-IC9 = og-linear:TL074: OP AMP
IC10 = texas:LM4041: PRECISION MICROPOWER SHUNT VOLTAGE REFERENCE
J1-J8 = og-pj301_variations:PJ301_THONKICONN
J9-J12 = og-pj301:PJ301_THONKICONN
JP1-JP4 = SparkFun:FIDUCIAL: Fiducial Alignment Points
JP5 = og-header:M05X2: Header 5x2 Standard 10-pin dual row 0.1" header. Commonly used with AVR-ISP. Use with Spark Fun Electronics SKU: PRT-00778
JP6 = SparkFun:M04: Header 4 Standard 4-pin 0.1" header. Use with straight break away headers (SKU : PRT-00116), right angle break away headers (PRT-00553), swiss pins (PRT-00743), machine pins (PRT-00117), and female headers (PRT-00115). Molex polarized connector foot print use with SKU : PRT-08231 with associated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
JP7 = SparkFun:M02: Header 2
L1 = og-rcl:L-US
L2-L4 = wuerth-elektronik:WE-CBF: SMD EMI Suppression Ferrite Beads
LED1-LED3 = og-leds:LED-BICOLOR-THROUGHHOLE
LED4-LED7 = og-leds:LED-BICOLOR-SHARED-THROUGHHOLE
Q1 = og-crystal:CRYSTAL: Crystal with 2 extra terminals for the metal LID (Abracon ABMM2 for example)
R1-R10 R13-R21 R25-R55 R61-R67 = rcl:R-US_: RESISTOR, American symbol
R11 R12 R22-R24 R56-R60 = og-pots:POT_US
SW1-SW3 = SparkFun:TAC_SWITCH: Momentary Switch Button commonly used for reset or general input. Spark Fun Electronics SKU : COM-00097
